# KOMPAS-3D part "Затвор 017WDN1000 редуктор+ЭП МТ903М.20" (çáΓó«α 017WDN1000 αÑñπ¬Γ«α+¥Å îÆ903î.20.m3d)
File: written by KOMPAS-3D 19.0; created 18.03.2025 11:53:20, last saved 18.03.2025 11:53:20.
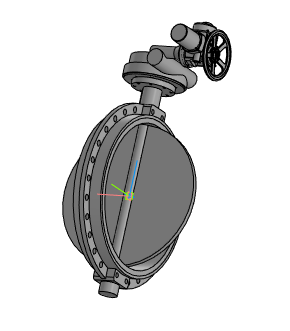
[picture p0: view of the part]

Document properties: Автор: Евгений; Полное имя файла: Затвор 017WDN1000 редуктор+ЭП МТ903М.20.a3d

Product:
- Part/product: Затвор 017WDN1000 редуктор+ЭП МТ903М.20
    Масса: 927.634

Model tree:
1. Операция без истории:1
